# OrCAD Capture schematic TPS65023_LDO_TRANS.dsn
size Custom; title: TPS65023x Power Management IC (PMIC) With 3 DC/DCs,; rev: 1.0; note: Datasheet: SLVS670L     EVM: SLVU193; note: Synchronous Step Down Converter
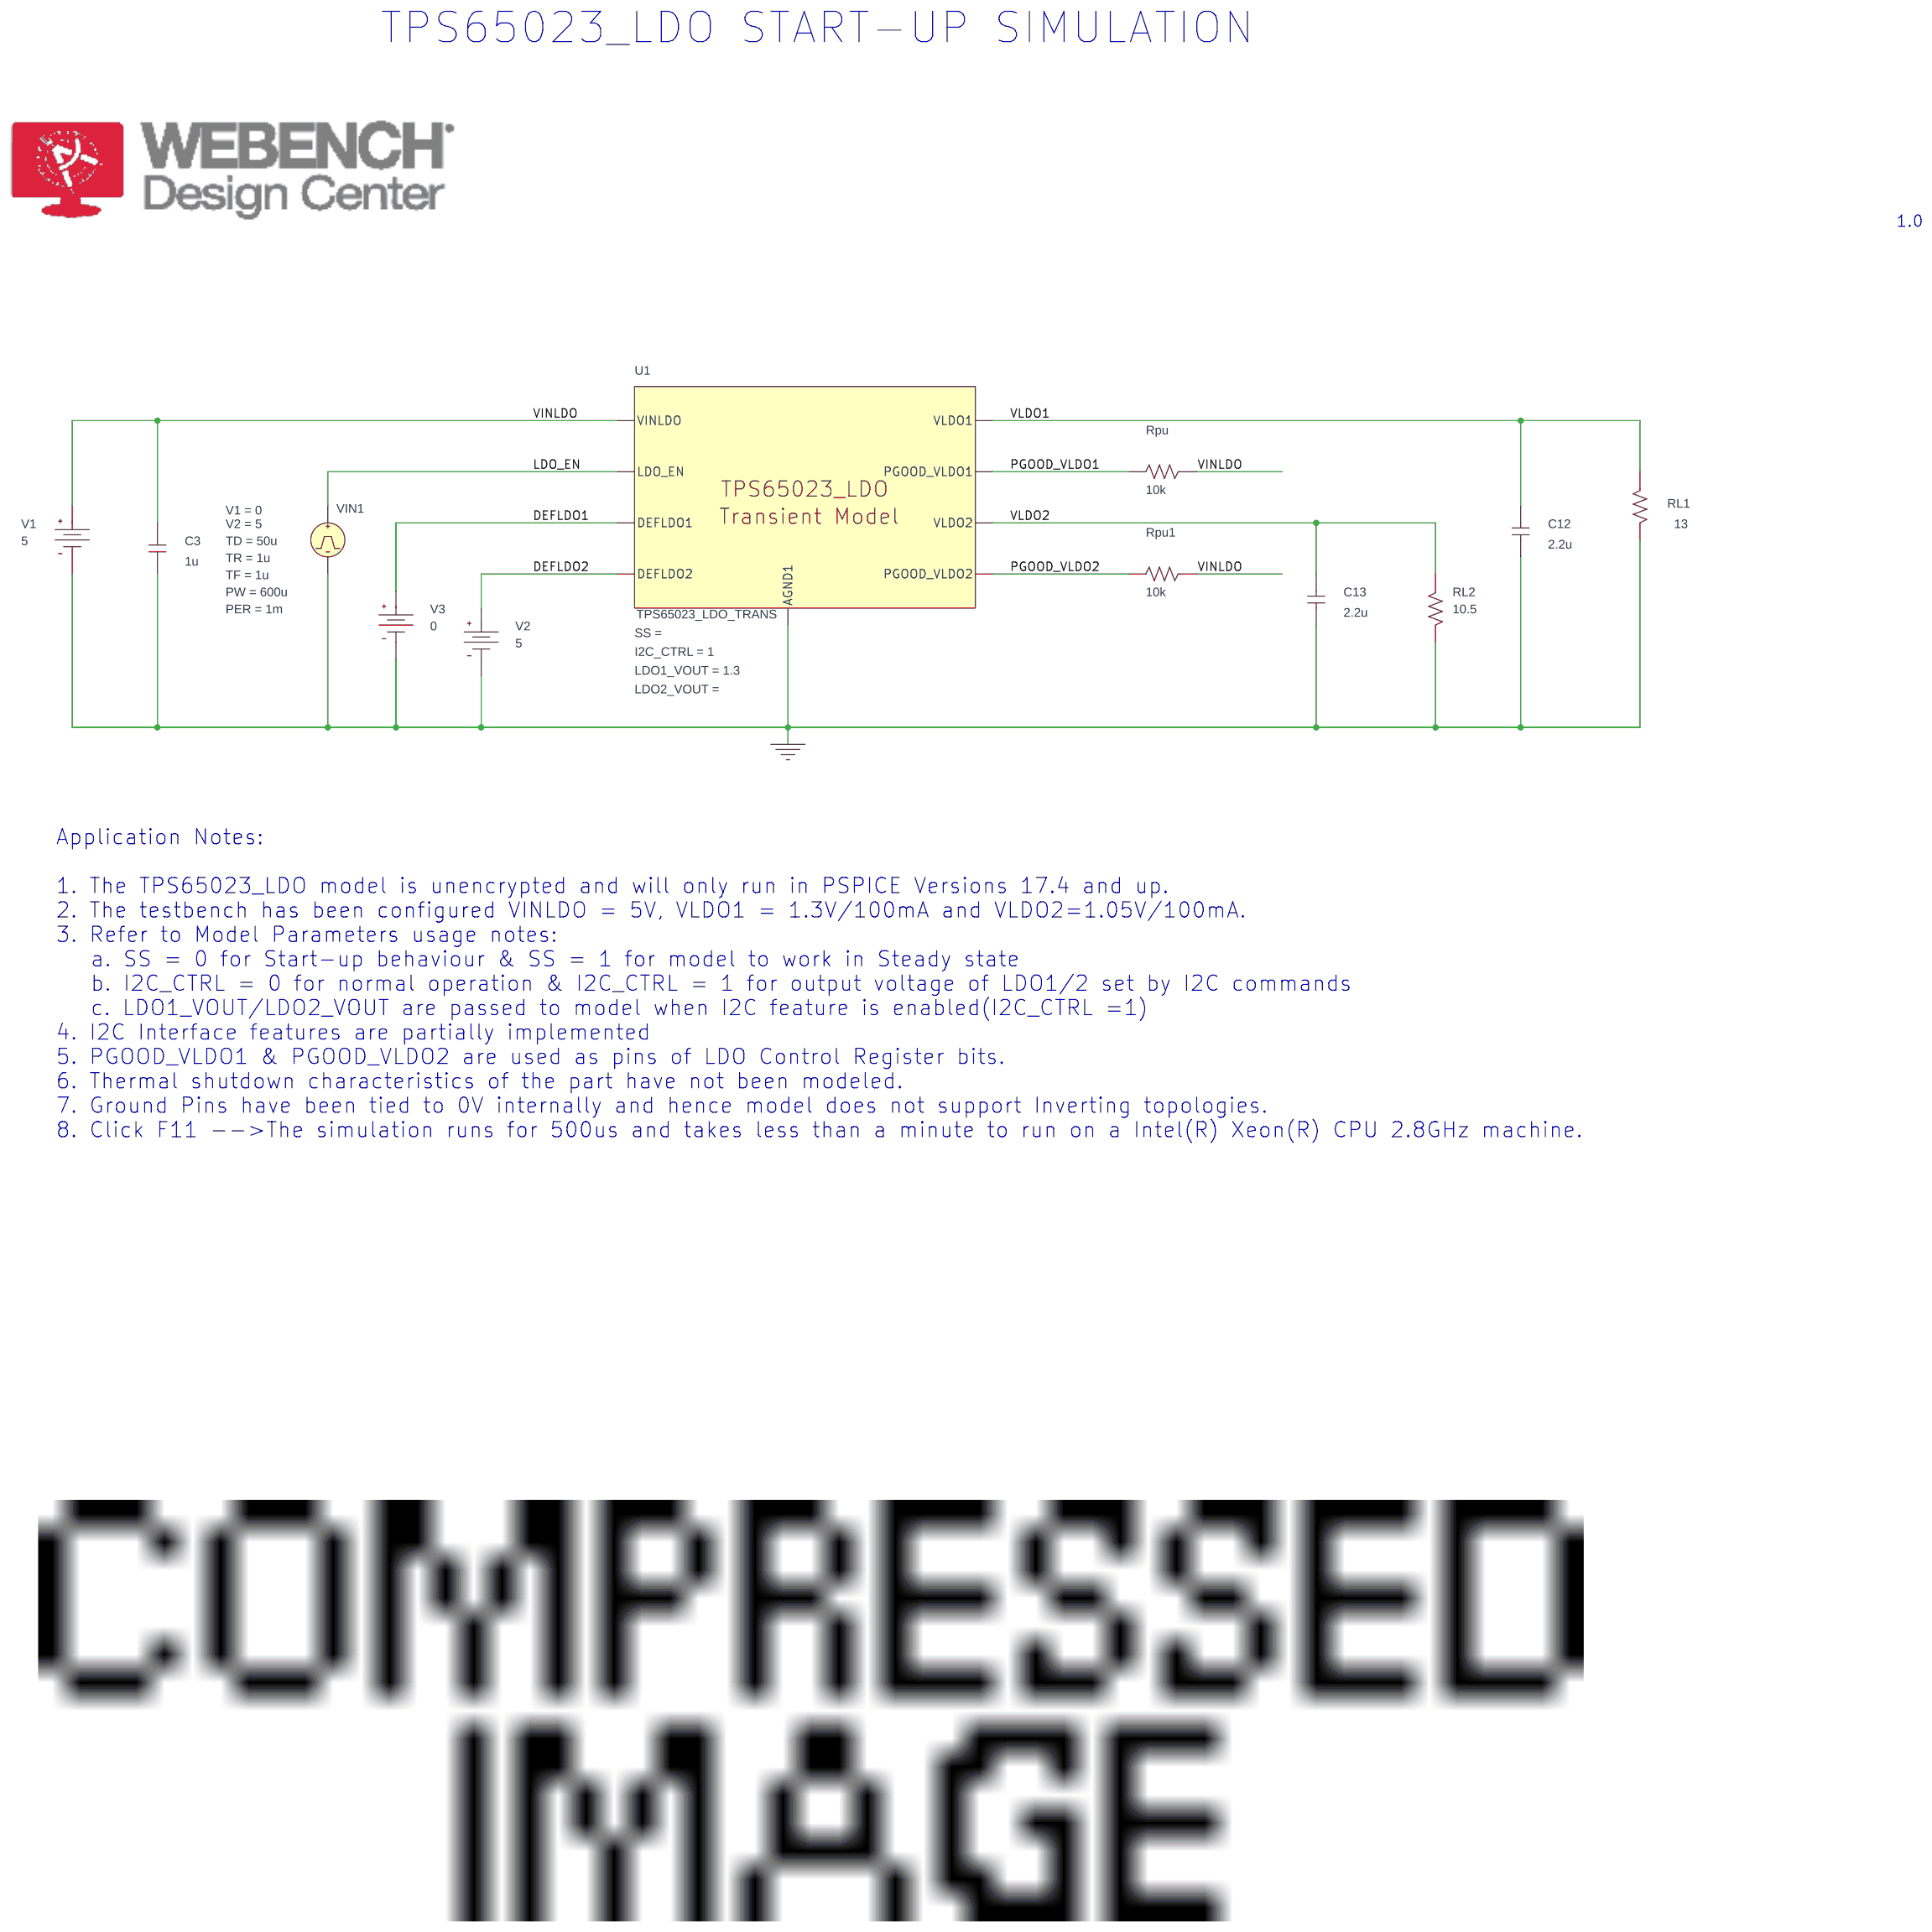
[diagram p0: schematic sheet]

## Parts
C3  1u  [RAD/CK05]
C12  2.2u  [RAD/CK05]
C13  2.2u  [RAD/CK05]
RL1  13  [AX/RC05]
RL2  10.5  [AX/RC05]
Rpu  10k  [AXRC05]
Rpu1  10k  [AXRC05]
U1  TPS65023_LDO_TRANS
V1  VDC
V2  VDC
V3  VDC
VIN1  VPULSE

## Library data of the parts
C3 C12 C13 = C
RL1 RL2 Rpu Rpu1 = R
U1 = TPS65023_LDO_TRANS: I2C_CTRL: 1; LDO1_VOUT: 1.3
V1 V2 = VDC: DC: 5
V3 = VDC: DC: 0
VIN1 = VPULSE: PER: 1m; PW: 600u; TD: 50u; TF: 1u; TR: 1u; V1: 0; V2: 5

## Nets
VINLDO: C3.2 Rpu.1 Rpu1.1 U1.VINLDO V1.0(+)
0: C3.1 C12.2 C13.2 RL1.2 RL2.2 U1.AGND1 V1.1(-) V2.1(-) V3.1(-) VIN1.2(-)
DEFLDO1: U1.DEFLDO1 V3.0(+)
DEFLDO2: U1.DEFLDO2 V2.0(+)
LDO_EN: U1.LDO_EN VIN1.1(+)
PGOOD_VLDO1: Rpu.2 U1.PGOOD_VLDO1
PGOOD_VLDO2: Rpu1.2 U1.PGOOD_VLDO2
VLDO1: C12.1 RL1.1 U1.VLDO1
VLDO2: C13.1 RL2.1 U1.VLDO2

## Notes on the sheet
- TPS65023_LDO START-UP SIMULATION
- 1.0
- Application Notes:
  1. The TPS65023_LDO model is unencrypted and will only run in PSPICE Versions 17.4 and up.
  2. The testbench has been configured VINLDO = 5V, VLDO1 = 1.3V/100mA and VLDO2=1.05V/100mA.
  3. Refer to Model Parameters usage notes:
     a. SS = 0 for Start-up behaviour & SS = 1 for model to work in Steady state
     b. I2C_CTRL = 0 for normal operation & I2C_CTRL = 1 for output voltage of LDO1/2 set by I2C commands
     c. LDO1_VOUT/LDO2_VOUT are passed to model when I2C feature is enabled(I2C_CTRL =1)
  4. I2C Interface features are partially implemented
  5. PGOOD_VLDO1 & PGOOD_VLDO2 are used as pins of LDO Control Register bits.
  6. Thermal shutdown characteristics of the part have not been modeled.
  7. Ground Pins have been tied to 0V internally and hence model does not support Inverting topologies.
  8. Click F11 -->The simulation runs for 500us and takes less than a minute to run on a Intel(R) Xeon(R) CPU 2.8GHz machine.
